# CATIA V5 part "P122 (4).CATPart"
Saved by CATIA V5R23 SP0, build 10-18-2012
Part number: 05-LICP-T02-E-S11-P122 (4)
Definition: butee a aiguilles
Description: butee_a_aiguilles_ax_5_40_60_04
Bounding box of the stored display mesh (mm): x 0 to 3, y -29.631 to 29.631, z -29.631 to 29.631
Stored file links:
  C:\wamp\www\COURS\CONCEPTION GMP1\TITRE 02-SEMESTRE 2\03-TP7-PRESSE MECANIQUE\eleve\P122 (4).CATPart
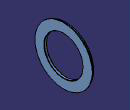
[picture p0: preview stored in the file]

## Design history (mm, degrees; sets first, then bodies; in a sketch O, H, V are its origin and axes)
Body1 (main body)
  Solid1: solid without history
